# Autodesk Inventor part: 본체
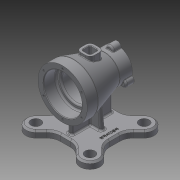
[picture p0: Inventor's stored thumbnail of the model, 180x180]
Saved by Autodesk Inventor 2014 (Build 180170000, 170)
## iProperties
Created: 2018-03
Part Number: 본체
Material: 일반
Document SubType Name: Modeling
Designer: 601-10
Density: 1 g/cm^3
Appearance: 기본값
Mass: 366.095 g
Surface Area: 851.87 cm^2
Volume: 366.095 cm^3
Author: 601-10
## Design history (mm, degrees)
sketch "스케치1"
  geometry: L1 (0, 50)-(0, -50); L2 (0, 50)-(45, 50); L3 (45, 50)-(45, 30); L4 (45, 30)-(27.5, -27); L5 (27.5, -27)-(27.5, -50); L6 (27.5, -50)-(0, -50); L7 (35, 50)-(35, 30); L8 (32, 27)-(29, 27); L9 (26, 24)-(26, -17); L10 (23, -20)-(23, -20); L11 (20, -23)-(20, -50); A1 r 3 centre (32, 30) between (32, 27) and (35, 30); A2 r 3 centre (29, 24) between (29, 27) and (26, 24); A3 r 3 centre (23, -17) between (23, -20) and (26, -17); A4 r 3 centre (23, -23) between (23, -20) and (20, -23); 6 further points
  constraints: 22 end point, 10 point on line, 8 point on circle, 8 tangent, 6 perpendicular, 4 centre point, 3 equal radius, 3 parallel, 1 coincident, 1 midpoint, 1 vertical
  dimensions: "d0" = 100 distance of L1.start L1.end; "d1" = 90 diameter of L3 L1; "d3" = 55 diameter of L5 L1; "d4" = 20 distance of L2.end L3.end; "d5" = 77 distance from line of L2 L4.end; "d6" = 70 diameter of L7 L1; "d7" = 23 distance between parallel lines of L2 L8; "d8" = 52 diameter of L9 L1; "d9" = 47 distance between parallel lines of L8 L10; "d10" = 40 diameter of L11 L1; "d11" = 30 distance between parallel lines of L6 L10 (derived); "d38" = 3 radius of A1
revolve "회전1" sketch "스케치1" stored, may be unused: angle "d12" = 90 deg
node "작업 평면1"
sketch "스케치2"
  geometry: L1 (-9.189, 45)-(9.189, 45); L2 (45, 9.189)-(45, -9.189); L3 (9.189, -45)-(-9.189, -45); L4 (-45, -9.189)-(-45, 9.189); L5 (-45, 45)-(45, -45); L6 (45, 45)-(-45, -45); L7 (-45, 50)-(45, 50) reference; L8 (49.497, 49.497)-(25.887, 25.887); L9 (36.77, 62.225)-(26.866, 52.322); L10 (52.322, 26.866)-(62.225, 36.77); L11 (0, 70)-(0, -70); L12 (-26.866, 52.322)-(-36.77, 62.225); L13 (-62.225, 36.77)-(-52.322, 26.866); L14 (-52.322, -26.866)-(-62.225, -36.77); L15 (-36.77, -62.225)-(-26.866, -52.322); L16 (26.866, -52.322)-(36.77, -62.225); L17 (62.225, -36.77)-(52.322, -26.866); L18 (-1, 37)-(1, 37); L19 (4, 34)-(4, -34); L20 (1, -37)-(-1, -37); L21 (-4, -34)-(-4, 34); L22 (-4, 37)-(4, -37); L23 (4, 37)-(-4, -37); C1 r 9 at (49.497, -49.497); C2 r 9 at (49.497, 49.497); C3 r 9 at (-49.497, 49.497); C4 r 9 at (-49.497, -49.497); A1 r 18 centre (49.497, 49.497) between (62.225, 36.77) and (36.77, 62.225); A2 r 18 centre (25.887, 25.887) between (13.159, 38.615) and (38.615, 13.159); A3 r 70 centre (0, 0) between (49.497, 49.497) and (0, 70); A4 r 18 centre (-49.497, 49.497) between (-36.77, 62.225) and (-62.225, 36.77); A5 r 18 centre (-49.497, -49.497) between (-62.225, -36.77) and (-36.77, -62.225); A6 r 18 centre (49.497, -49.497) between (36.77, -62.225) and (62.225, -36.77); A7 r 25 centre (70, 9.189) between (52.322, 26.866) and (45, 9.189); A8 r 25 centre (70, -9.189) between (45, -9.189) and (52.322, -26.866); A9 r 25 centre (9.189, -70) between (26.866, -52.322) and (9.189, -45); A10 r 25 centre (-9.189, -70) between (-9.189, -45) and (-26.866, -52.322); A11 r 25 centre (-70, -9.189) between (-52.322, -26.866) and (-45, -9.189); A12 r 25 centre (-70, 9.189) between (-45, 9.189) and (-52.322, 26.866); A13 r 25 centre (-9.189, 70) between (-26.866, 52.322) and (-9.189, 45); A14 r 25 centre (9.189, 70) between (9.189, 45) and (26.866, 52.322); A15 r 3 centre (1, 34) between (4, 34) and (1, 37); A16 r 3 centre (-1, 34) between (-1, 37) and (-4, 34); A17 r 3 centre (-1, -34) between (-4, -34) and (-1, -37); A18 r 3 centre (1, -34) between (1, -37) and (4, -34); 10 further points
  constraints: 46 end point, 37 point on circle, 28 tangent, 25 point on line, 22 centre point, 9 equal radius, 6 midpoint, 5 parallel, 3 coincident, 3 perpendicular, 2 horizontal, 42 other
  dimensions: "d14" = 90 distance of L5.end L6.end; "d15" = 90 distance of L6.start L5.end; "d16" = 50 distance from line of L7 point (0, 0); "d17" = 36 diameter of A2; "d18" = 140 diameter of A3; "d19" = 45 deg angle of L11 L8; "d22" = 360 deg dimension on A3.centre L8.start (derived); "d24" = 25 radius of A7; "d25" = 25 radius of A11; "d26" = 18 diameter of C1; "d29" = 360 deg dimension on A3.centre C1.centre (derived); "d31" = 8 distance of L22.end L23.end; "d32" = 74 distance of L23.start L22.end; "d33" = 3 radius of A15
extrude "돌출1" join sketch "스케치2" distance "d34" = 12; taper "d35" = 0 deg
extrude "돌출2" join sketch "스케치2" stored distance "d36" = 0; taper "d37" = 0 deg
sketch "스케치3"
  geometry: L1 (36.77, -70)-(26.866, -70) reference; L2 (-26.866, -70)-(-36.77, -70) reference; L3 (24, -70)-(19.844, -22.499); L4 (-19.844, -22.499)-(-24, -70); L5 (-24, -70)-(24, -70); A1 r 30 centre (0, 0) between (-19.844, -22.499) and (19.844, -22.499); 1 further point
  constraints: 6 end point, 2 point on circle, 2 point on line, 1 centre point, 1 coincident, 1 collinear
  dimensions: "d39" = 24 horizontal distance of point (0, 0) L3.start; "d40" = 95 deg angle of L1 L3; "d41" = 24 horizontal distance of point (0, 0) L4.end; "d42" = 95 deg angle of L2 L4; "d43" = 60 diameter of A1
extrude "돌출3" join sketch "스케치3" stored distance "d44" = 8; taper "d45" = 0 deg
sketch "스케치4"
  geometry: C1 r 7 at (0, 27.5); C2 r 7 at (-23.816, -13.75); C3 r 7 at (23.816, -13.75); 1 further point
  constraints: 3 centre point, 2 vertical alignment, 8 other
  dimensions: "d47" = 14 diameter of C1; "d50" = 360 deg dimension on point (0, 0) C1.centre (derived)
extrude "돌출4" join sketch "스케치4" distance "d52" = 15; taper "d53" = 0 deg
sketch "스케치5"
  geometry: A1 r 7 centre (0, 0) between (6.943, -0.891) and (-6.943, -0.891) reference; A2 r 7 centre (-23.816, -41.25) between (-26.516, -34.792) and (-19.573, -46.817) reference; A3 r 7 centre (23.816, -41.25) between (19.573, -46.817) and (26.516, -34.792) reference; 3 further points
  constraints: 3 coincident
hole "구멍1" sketch "스케치5" at (0, 0), (23.816, -41.25), (-23.816, -41.25) diameter "d54" = 3.242; stored, may be unused: countersink angle "d58" = 90 deg, drill point angle "d60" = 118 deg; dims "d55" = 9, "d56" = 4, "d57" = 2, "d59" = 11
node "작업 평면2"
sketch "스케치6"
  geometry: L1 (4.5, 12.5)-(-4.5, 12.5); L2 (-12.5, 4.5)-(-12.5, -4.5); L3 (-4.5, -12.5)-(4.5, -12.5); L4 (12.5, -4.5)-(12.5, 4.5); L5 (12.5, 12.5)-(-12.5, -12.5); L6 (-12.5, 12.5)-(12.5, -12.5); L7 (-4.5, 7.5)-(4.5, 7.5); L8 (7.5, 4.5)-(7.5, -4.5); L9 (4.5, -7.5)-(-4.5, -7.5); L10 (-7.5, -4.5)-(-7.5, 4.5); L11 (-7.5, 7.5)-(7.5, -7.5); L12 (7.5, 7.5)-(-7.5, -7.5); A1 r 8 centre (4.5, 4.5) between (12.5, 4.5) and (4.5, 12.5); A2 r 8 centre (4.5, -4.5) between (4.5, -12.5) and (12.5, -4.5); A3 r 8 centre (-4.5, -4.5) between (-12.5, -4.5) and (-4.5, -12.5); A4 r 8 centre (-4.5, 4.5) between (-4.5, 12.5) and (-12.5, 4.5); A5 r 3 centre (4.5, 4.5) between (7.5, 4.5) and (4.5, 7.5); A6 r 3 centre (-4.5, 4.5) between (-4.5, 7.5) and (-7.5, 4.5); A7 r 3 centre (-4.5, -4.5) between (-7.5, -4.5) and (-4.5, -7.5); A8 r 3 centre (4.5, -4.5) between (4.5, -7.5) and (7.5, -4.5); 1 further point
  constraints: 24 end point, 16 point on circle, 16 point on line, 16 tangent, 8 centre point, 6 equal radius, 4 midpoint, 4 parallel, 2 horizontal, 2 perpendicular
  dimensions: "d62" = 25 distance of L6.end L5.end; "d63" = 25 distance of L5.end L6.start; "d64" = 15 distance of L11.end L12.end; "d65" = 15 distance of L12.start L11.end; "d66" = 8 radius of A1; "d67" = 3 radius of A5
extrude "돌출5" join sketch "스케치6" stored distance "d68" = 15; taper "d69" = 0 deg
extrude "돌출6" cut sketch "스케치6" stored distance "d70" = 15; taper "d71" = 0 deg
sketch "스케치7" dims "d72" = 80
  geometry: C1 r 35 at (0, 0) reference; C2 r 45 at (0, 0) reference; 2 further points
  constraints: 2 vertical alignment, 1 coincident, 2 other
hole "구멍2" sketch "스케치7" at (0, 40) diameter "d73" = 3.242; stored, may be unused: countersink angle "d77" = 90 deg, drill point angle "d79" = 118 deg; dims "d74" = 9, "d75" = 4, "d76" = 2, "d78" = 11
chamfer "모따기1" distance "d83" = 1; stored, may be unused: second distance "d84" = 2, angle "d85" = 45 deg
chamfer "모따기2" distance "d86" = 3; stored, may be unused: second distance "d87" = 2, angle "d88" = 45 deg
fillet "모깎기2" dims "d90" = 3
fillet "모깎기3" dims "d91" = 1
node "작업 평면3"
sketch "스케치9"
  geometry: L1 (9.189, 45)-(-9.189, 45) reference; 2 further points
  constraints: 1 other
  dimensions: "d95" = 35 distance of point (0, 0) point (35, 0); "d96" = 45 distance from line of L1 point (35, 0)
feature "엠보싱1" sketch "스케치9" dims "d8" = 52, "d97" = 0.5, "d98" = 0
node "솔리드1"
pattern_circular "원형 패턴1" dims angle "d81" = 360 deg
other parameters: "d13" = -82, "d61" = 45, "d94" = 5
